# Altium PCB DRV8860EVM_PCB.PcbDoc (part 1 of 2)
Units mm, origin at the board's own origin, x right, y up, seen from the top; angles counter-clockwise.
Board outline 101 x 60 mm, 2 copper layers (Top Layer, Bottom Layer); 122 components, 87 nets, 449 pads, 90 vias.
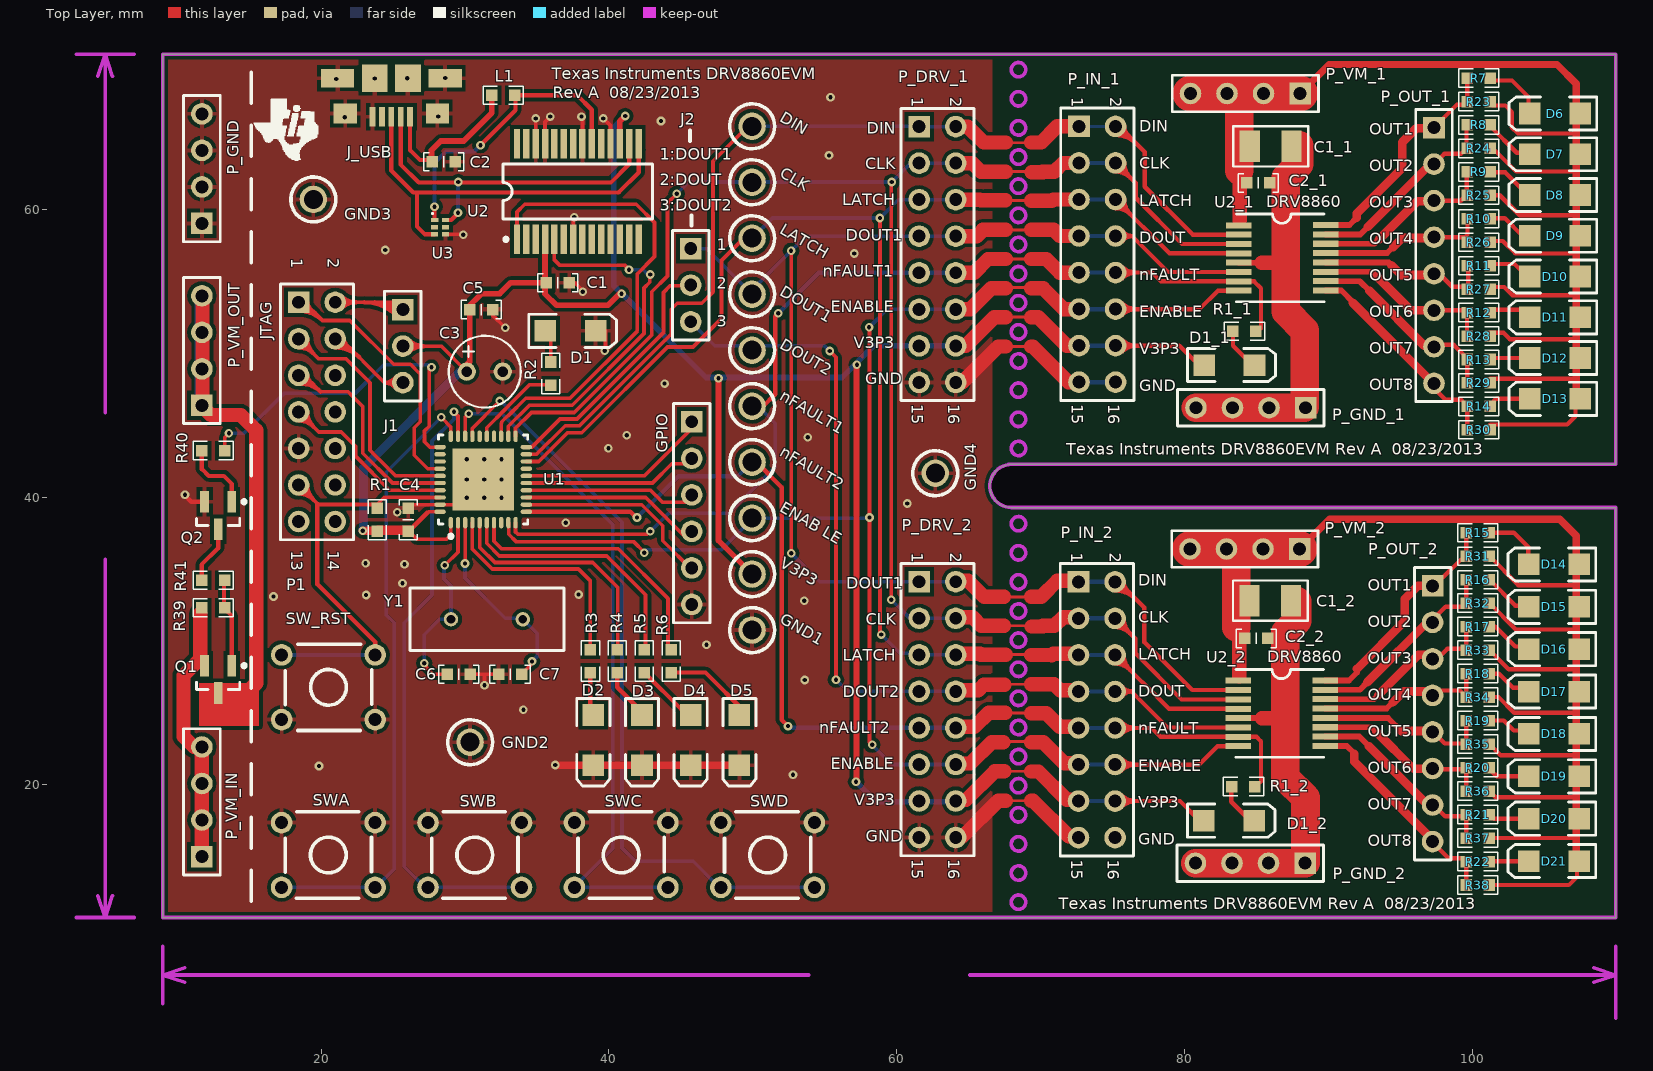
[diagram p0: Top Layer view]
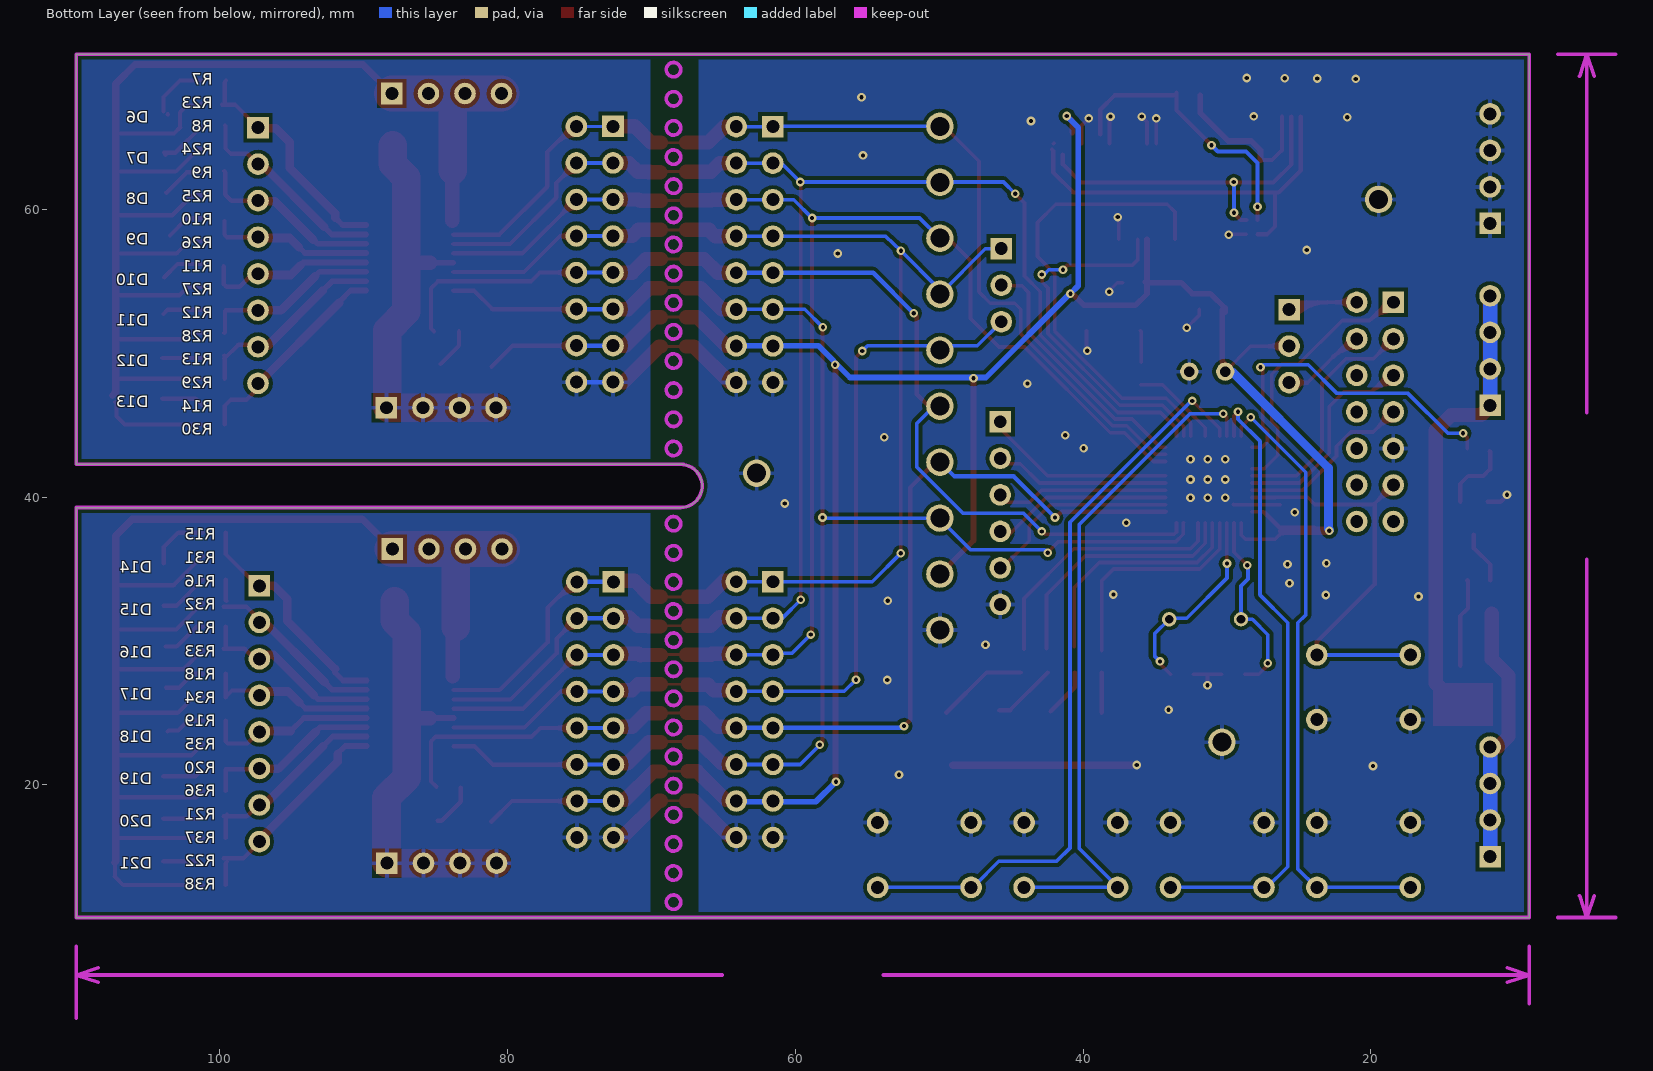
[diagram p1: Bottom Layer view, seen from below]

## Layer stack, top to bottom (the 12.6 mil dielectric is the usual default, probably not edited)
Top Layer: signal copper 0.0356
Dielectric: dielectric 0.32, FR-4, Dk 4.8
Bottom Layer: signal copper 0.0356

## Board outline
8.979,10.787 8.979,70.787 109.979,70.787 109.979,42.287 67.979,42.287 ccw(c67.979,40.787) 67.979,39.287 109.979,39.287 109.979,10.787

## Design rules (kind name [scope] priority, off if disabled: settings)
Clearance [All] p1: gap=0.2
PolygonConnect [(InPadClass('All Pads'))] p1: connectstyle=Relief reliefconductorwidth=0.3 reliefentries=4 polygonreliefangle="90 Angle" airgapwidth=0.254
PolygonConnect PolygonConnect_1 [All] p2: connectstyle=Direct reliefconductorwidth=0.254 reliefentries=4 polygonreliefangle="90 Angle" airgapwidth=0.254
RoutingVias [All] p1: holewidth=0.3 width=0.6 viastyle="Through Hole" minholewidth=0.25 minwidth=0.25 maxholewidth=0.711 maxwidth=1.27
SilkscreenOverComponentPads [All] p1: minsilkscreentomaskgap=0.254
SolderMaskExpansion [All] p1: expansion=0.102
Width [All] p1: maxlimit=3 minlimit=0.2 preferedwidth=0.254
27 further rules are at their usual default settings.

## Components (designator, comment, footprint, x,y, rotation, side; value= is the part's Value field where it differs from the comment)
C1 "Cap" C0603 36.437,54.907 r180 top
C1_1 "" 1210 84.546,64.398 r0 top
C1_2 "" 1210 84.519,32.809 r0 top
C2 "Cap" C0603 28.526,63.328 r180 top
C2_1 "" C0603 85.13,61.856 r0 top
C2_2 "" C0603 84.997,30.186 r0 top
C3 "Cap Pol1" CAP5MM 30.117,48.731 r0 top
C4 "Cap" C0603 26.053,38.444 r270 top
C5 "Cap" C0603 31.133,53.049 r0 top
C6 "Cap" C0603 29.567,27.7 r180 top
C7 "Cap" C0603 33.123,27.7 r0 top
CLK "IN1" TESTP 49.953,61.898 r0 top
D1 "Status" 3.2X1.6X1.1 37.324,51.57 r0 top
D1_1 "nFAULT" 3.2X1.6X1.1 83.126,49.191 r0 top
D1_2 "FAULTn" 3.2X1.6X1.1 83.111,17.516 r0 top
D2 "Status" 3.2X1.6X1.1 38.911,23.116 r270 top
D3 "Status" 3.2X1.6X1.1 42.296,23.116 r270 top
D4 "Status" 3.2X1.6X1.1 45.682,23.116 r270 top
D5 "Status" 3.2X1.6X1.1 49.068,23.116 r270 top
D6 "" 3.2X1.6X1.1 105.771,66.678 r180 top
D7 "" 3.2X1.6X1.1 105.771,63.845 r180 top
D8 "" 3.2X1.6X1.1 105.771,61.012 r180 top
D9 "" 3.2X1.6X1.1 105.771,58.179 r180 top
D10 "" 3.2X1.6X1.1 105.771,55.346 r180 top
D11 "" 3.2X1.6X1.1 105.771,52.513 r180 top
D12 "" 3.2X1.6X1.1 105.771,49.68 r180 top
D13 "" 3.2X1.6X1.1 105.771,46.847 r180 top
D14 "" 3.2X1.6X1.1 105.699,35.332 r180 top
D15 "" 3.2X1.6X1.1 105.699,32.385 r180 top
D16 "" 3.2X1.6X1.1 105.699,29.439 r180 top
D17 "" 3.2X1.6X1.1 105.699,26.493 r180 top
D18 "" 3.2X1.6X1.1 105.699,23.547 r180 top
D19 "" 3.2X1.6X1.1 105.699,20.601 r180 top
D20 "" 3.2X1.6X1.1 105.699,17.654 r180 top
D21 "" 3.2X1.6X1.1 105.699,14.708 r180 top
DIN "IN1" TESTP 49.953,65.79 r0 top
DOUT1 "IN1" TESTP 49.953,54.115 r90 top
DOUT2 "IN1" TESTP 49.953,50.223 r90 top
"ENAB LE" "IN1" TESTP 49.953,38.548 r90 top
GND1 "IN1" TESTP 49.953,30.765 r0 top
GND2 "IN1" TESTP 30.351,22.973 r90 top
GND3 "IN1" TESTP 19.451,60.706 r90 top
GND4 "IN1" TESTP 62.686,41.674 r90 top
GPIO "Header 6" HDR1X6 45.756,45.25 r270 top
J1 "PWR Select" HDR1X3 25.672,53.049 r270 top
J2 "DOUT Select" HDR1X3 45.685,57.283 r270 top
J_USB "USB Mini B Connector" "Micro USB AB" 24.87,66.455 r180 top
L1 "" R0603 32.643,67.94 r0 top
LATCH "IN1" TESTP 49.953,58.007 r90 top
nFAULT1 "IN1" TESTP 49.953,46.332 r90 top
nFAULT2 "IN1" TESTP 49.953,42.44 r90 top
P1 "JTAG" HDR2X7 18.433,53.557 r270 top
P_DRV_1 "Header 8X2" HDR2X8 61.569,65.767 r270 top
P_DRV_2 "Header 8X2" HDR2X8 61.569,34.129 r270 top
P_GND "Header 4" HDR1X4 11.705,59.036 r90 top
P_GND_1 "Header 4" HDR1X4 88.427,46.223 r180 top
P_GND_2 "Header 4" HDR1X4 88.392,14.562 r180 top
P_IN_1 "Header 8X2" HDR2X8 72.679,65.781 r270 top
P_IN_2 "Header 8X2" HDR2X8 72.644,34.12 r270 top
P_OUT_1 "TSW-108-07-G-S" HDR1X8 97.354,65.699 r270 top
P_OUT_2 "TSW-108-07-G-S" HDR1X8 97.259,33.847 r270 top
P_VM_1 "Header 4" HDR1X4 88.046,68.067 r180 top
P_VM_2 "Header 4" HDR1X4 88.011,36.406 r180 top
P_VM_IN "Header 4" HDR1X4 11.705,15.023 r90 top
P_VM_OUT "Header 4" HDR1X4 11.705,46.386 r90 top
Q1 "Si2319CDS" SOT-23 12.838,27.344 r270 top
Q2 "2N3904" SOT-23 12.838,38.738 r270 top
R1 "" R0603 23.894,38.444 r90 top
R1_1 "330" R0603 84.18,51.546 r180 top
R1_2 "330" R0603 84.111,19.886 r180 top
R2 "Res2" R0603 35.959,48.604 r270 top
R3 "Res2" R0603 38.71,28.616 r90 top
R4 "Res2" R0603 40.584,28.616 r90 top
R5 "Res2" R0603 42.457,28.616 r90 top
R6 "Res2" R0603 44.331,28.616 r90 top
R7 "10k" R0603 100.475,69.141 r180 top
R8 "10k" R0603 100.475,65.88 r180 top
R9 "10k" R0603 100.475,62.62 r180 top
R10 "10k" R0603 100.475,59.359 r180 top
R11 "10k" R0603 100.475,56.099 r180 top
R12 "10k" R0603 100.475,52.838 r180 top
R13 "10k" R0603 100.475,49.578 r180 top
R14 "10k" R0603 100.475,46.317 r180 top
R15 "10k" R0603 100.405,37.54 r180 top
R16 "10k" R0603 100.405,34.274 r180 top
R17 "10k" R0603 100.405,31.009 r180 top
R18 "10k" R0603 100.405,27.743 r180 top
R19 "10k" R0603 100.405,24.477 r180 top
R20 "10k" R0603 100.405,21.211 r180 top
R21 "10k" R0603 100.405,17.945 r180 top
R22 "10k" R0603 100.405,14.68 r180 top
R23 "27k" r0603 100.475,67.511 r0 top
R24 "27k" r0603 100.475,64.25 r0 top
R25 "27k" r0603 100.475,60.989 r0 top
R26 "27k" r0603 100.475,57.729 r0 top
R27 "27k" r0603 100.475,54.468 r0 top
R28 "27k" r0603 100.475,51.208 r0 top
R29 "27k" r0603 100.475,47.947 r0 top
R30 "27k" r0603 100.475,44.687 r0 top
R31 "27k" r0603 100.405,35.907 r0 top
R32 "27k" r0603 100.405,32.642 r0 top
R33 "27k" r0603 100.405,29.376 r0 top
R34 "27k" r0603 100.405,26.11 r0 top
R35 "27k" r0603 100.405,22.844 r0 top
R36 "27k" r0603 100.405,19.578 r0 top
R37 "27k" r0603 100.405,16.313 r0 top
R38 "27k" r0603 100.405,13.047 r0 top
R39 "" r0603 12.486,32.317 r180 top
R40 "" r0603 12.486,43.244 r180 top
R41 "" r0603 12.486,34.231 r0 top
SW_RST "MCU-RST" SWWW 20.502,26.792 r180 top
SWA "MCU-RST" SWWW 20.494,15.132 r0 top
SWB "MCU-RST" SWWW 30.673,15.132 r0 top
SWC "MCU-RST" SWWW 40.852,15.132 r0 top
SWD "MCU-RST" SWWW 51.03,15.132 r0 top
U1 "MSP430F2350" QFN40 31.26,41.238 r90 top
U2 "FT232RL-Reel" SSOP28 37.834,61.257 r0 top
U2_1 "Wolfteeth" WT 83.601,59.558 r270 top
U2_2 "Wolfteeth" WT 83.566,27.897 r270 top
U3 "TPD2E001DRYRG4" DRY0006A 28.26,58.776 r0 top
V3P3 "IN1" TESTP 49.953,34.657 r90 top
Y1 "8 MHZ" XTAL6 34.012,31.51 r180 top

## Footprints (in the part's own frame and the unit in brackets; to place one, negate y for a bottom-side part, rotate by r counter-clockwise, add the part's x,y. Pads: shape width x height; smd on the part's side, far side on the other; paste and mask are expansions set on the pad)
3.2X1.6X1.1 [mm] "SMT LED; 2 Flat Leads"
  rect 1.5x1.5 smd: 1(-1.75,0) 2(1.75,0)
  silkscreen extent -2.9,-1.15 3.2,1.15
1210 [mm]
  rect 1.4x2.2 smd: 1(0,0) 2(2.9,0)
  silkscreen extent -1.14,-1.4 4.06,1.4
C0603 [mm]
  rect 0.8x0.8 smd: 1(-0.8,0) 2(0.8,0)
  silkscreen extent -1.4,-0.64 1.4,0.64
CAP5MM [mil]
  round 50 hole 28: 1(0,0) 2(98.43,0)
  silkscreen extent -49,-98 148,98
DRY0006A [mm] "PSON, 6-Leads, Body 1x1.45mm, Pitch 0.5mm, TI Recommended"
  rect 0.52x0.3 smd paste+0 mask+0.05: 1(-0.385,0.5)
  rect 0.49x0.3 smd paste+0 mask+0.05: 2(-0.385,0) 3(-0.385,-0.5) 4(0.385,-0.5) 5(0.385,0) 6(0.385,0.5)
  silkscreen extent -0.57,0.9 -0.48,1, body extent -0.53,-0.75 0.53,0.75, height 0.6
HDR1X3 [mm] "Connector; Header; 3 Position"
  rect 1.5x1.5 hole 0.9: 1(0,0)
  round 1.5 hole 0.9: 2(2.54,0) 3(5.08,0)
  silkscreen extent -1.27,-1.27 6.35,1.27
HDR1X4 [mm] "Connector; Header; 4 Position"
  rect 1.5x1.5 hole 0.9: 1(0,0)
  round 1.5 hole 0.9: 2(2.54,0) 3(5.08,0) 4(7.62,0)
  silkscreen extent -1.27,-1.27 8.89,1.27
HDR1X6 [mm] "Connector; Header; 6 Position"
  rect 1.5x1.5 hole 0.9: 1(0,0)
  round 1.5 hole 0.9: 2(2.54,0) 3(5.08,0) 4(7.62,0) 5(10.16,0) 6(12.7,0)
  silkscreen extent -1.27,-1.27 13.97,1.27
HDR1X8 [mm] "Connector; Header; 8 Position"
  rect 1.5x1.5 hole 0.9: 1(0,0)
  round 1.5 hole 0.9: 2(2.54,0) 3(5.08,0) 4(7.62,0) 5(10.16,0) 6(12.7,0) 7(15.24,0) 8(17.78,0)
  silkscreen extent -1.27,-1.27 19.05,1.27
HDR2X7 [mm] "Connector; Header; 7x2 Position"
  rect 1.5x1.5 hole 0.9: 1(0,0)
  round 1.5 hole 0.9: 2(0,2.54) 3(2.54,0) 4(2.54,2.54) 5(5.08,0) 6(5.08,2.54) 7(7.62,0) 8(7.62,2.54) 9(10.16,0) 10(10.16,2.54) 11(12.7,0) 12(12.7,2.54) 13(15.24,0) 14(15.24,2.54)
  silkscreen extent -1.27,-1.27 16.51,3.81
HDR2X8 [mm] "Connector; Header; 8x2 Position"
  rect 1.5x1.5 hole 0.9: 1(0,0)
  round 1.5 hole 0.9: 2(0,2.54) 3(2.54,0) 4(2.54,2.54) 5(5.08,0) 6(5.08,2.54) 7(7.62,0) 8(7.62,2.54) 9(10.16,0) 10(10.16,2.54) 11(12.7,0) 12(12.7,2.54) 13(15.24,0) 14(15.24,2.54) 15(17.78,0) 16(17.78,2.54)
  silkscreen extent -1.27,-1.27 19.05,3.81
"Micro USB AB" [mm]
  rect 0.4x1.35 smd: 1(-1.3,0) 2(-0.65,0) 3(0,0) 4(0.65,0) 5(1.3,0)
  rect 2.3x1.3 smd: 5(-3.75,-2.675) 5(3.75,-2.675)
  rect 1.6x1.4 smd: 5(-3.2,-0.225) 5(3.2,-0.225)
  rect 1.8x1.9 smd: 5(-1.15,-2.675) 5(1.15,-2.675)
QFN40 [mm] "QFN, 40-Leads, Body 6x6mm, Pitch 0.5mm, IPC Medium Density"
  oval 0.8x0.3 smd: 1(-3,2.25) 2(-3,1.75) 3(-3,1.25) 4(-3,0.75) 5(-3,0.25) 6(-3,-0.25) 7(-3,-0.75) 8(-3,-1.25) 9(-3,-1.75) 10(-3,-2.25) 21(3,-2.25) 22(3,-1.75) 23(3,-1.25) 24(3,-0.75) 25(3,-0.25) 26(3,0.25) 27(3,0.75) 28(3,1.25) 29(3,1.75) 30(3,2.25)
  oval 0.3x0.8 smd: 11(-2.25,-3) 12(-1.75,-3) 13(-1.25,-3) 14(-0.75,-3) 15(-0.25,-3) 16(0.25,-3) 17(0.75,-3) 18(1.25,-3) 19(1.75,-3) 20(2.25,-3) 31(2.25,3) 32(1.75,3) 33(1.25,3) 34(0.75,3) 35(0.25,3) 36(-0.25,3) 37(-0.75,3) 38(-1.25,3) 39(-1.75,3) 40(-2.25,3)
  rect 4.3x4.3 smd: 41(0,0)
  silkscreen extent -4.07,-3.1 3.1,3.1, body extent -3.08,-3.08 3.08,3.08, height 0.8
R0603 [mm]
  rect 0.8x0.8 smd: 1(-0.8,0) 2(0.8,0)
  silkscreen extent -1.4,-0.64 1.4,0.64
r0603 [mm]
  rect 0.8x0.8 smd: 1(-0.8,0) 2(0.8,0)
  silkscreen extent -1.4,-0.64 1.4,0.64
SOT-23 [mm] "SOT23, 3-Leads, Body 2.9x1.3mm, Pitch 0.95mm, Lead Span 2.5mm, IPC Medium Density"
  rect 1.5x0.6 smd: 1(-0.95,0.95) 2(-0.95,-0.95) 3(0.95,0)
  silkscreen extent -1.07,-1.5 0.7,1.93, body extent -1.16,-1.45 1.21,1.45, height 1
SSOP28 [mm] "SSOP; 28 Leads; Body Width 5.3 mm; Pitch 0.65 mm"
  rect 0.45x2.05 smd: 1(-4.225,-3.325) 2(-3.575,-3.325) 3(-2.925,-3.325) 4(-2.275,-3.325) 5(-1.625,-3.325) 6(-0.975,-3.325) 7(-0.325,-3.325) 8(0.325,-3.325) 9(0.975,-3.325) 10(1.625,-3.325) 11(2.275,-3.325) 12(2.925,-3.325) 13(3.575,-3.325) 14(4.225,-3.325) 15(4.225,3.325) 16(3.575,3.325) 17(2.925,3.325) 18(2.275,3.325) 19(1.625,3.325) 20(0.975,3.325) 21(0.325,3.325) 22(-0.325,3.325) 23(-0.975,3.325) 24(-1.625,3.325) 25(-2.275,3.325) 26(-2.925,3.325) 27(-3.575,3.325) 28(-4.225,3.325)
  silkscreen extent -5.2,-3.45 5.2,1.9
SWWW [mm]
  round 1.5 hole 0.9: 1(-3.25,2.25) 1(3.25,2.25) 2(-3.25,-2.25) 2(3.25,-2.25)
  silkscreen extent -3,-3 3,3
TESTP [mil] "Glass Beaded Test Point"
  round 75 hole 52: 1(0,0)
  silkscreen extent -61,-61 62,61
WT [mm]
  rect 0.42x1.78 smd: 1(0.65,0.173) 2(1.3,0.173) 3(1.95,0.173) 4(2.6,0.173) 5(3.25,0.173) 6(3.9,0.173) 7(4.55,0.173) 8(5.2,0.173) 9(5.185,6.223) 10(4.535,6.223) 11(3.885,6.223) 12(3.235,6.223) 13(2.585,6.223) 14(1.935,6.223) 15(1.285,6.223) 16(0.635,6.223)
  silkscreen extent -0.13,0.03 5.97,6.1
XTAL6 [mm]
  round 1 hole 0.6: 1(-0.004,-0.007) 2(4.992,-0.01)
  silkscreen extent -2.87,-2.18 7.85,2.16

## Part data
C1 C2 C4 C5: "CAP .10UF 50V CERAMIC X7R 0805"
C1_1 C1_2: library part "Cap Pol1", "CAP ALUM 10UF 25V 20% RADIAL"
C2_1 C2_2: library part Cap, "Capacitor"
C3: "CAP ALUM 10UF 25V 20% RADIAL"
C6 C7: "CAP CERAMIC 33PF 50V NP0 0805"
CLK DIN DOUT1 DOUT2 "ENAB LE" GND1 GND2 GND3 GND4 LATCH nFAULT1 nFAULT2 V3P3: library part "TEST POINT", "PC TEST POINT MINIATURE SMT"
D1 D2 D3 D4 D5: library part LED3, "LED RED FACE UP 1206"
D1_1 D1_2 D6 D7 D8 D9 D10 D11 D12 D13 D14 D15 D16 D17 D18 D19 D20 D21: library part LED2, "LED RED FACE UP 1206"
GPIO: "Header, 6-Pin"
J1 J2: library part "Header 3", "CONN HEADER .100 SNGL STR 3POS"
J_USB: library part "USB Mini B Recepticle", "CONN RCPT MICRO USB TYPE AB"
L1: library part Inductor, "FERRITE 1.5A 40 OHM 0805 SMD"
P1: library part "Header 7X2H", "CONN HEADER .100 DUAL STR 14POS"
P_DRV_1 P_DRV_2 P_IN_1 P_IN_2: "Header, 8-Pin, Dual row"
P_GND P_GND_1 P_GND_2 P_VM_1 P_VM_2 P_VM_IN P_VM_OUT: "Header, 4-Pin"
P_OUT_1 P_OUT_2: "Header, TH, 100mil, 8x1, Gold plated, 230 mil above insulator"
Q1: library part SI2319DS-T1-E3, "MOSFET, P-CH, -40V, -2.3A, SOT-23"
Q2: library part "MMBT3904, Fairchild Semiconductor", "Transistor, NPN, 40V, 0.2A, SOT-23"
R1 R39 R40 R41: library part Res1, "RES 3.3K OHM 1/10W 5% 0603 SMD"
R1_1 R1_2 R7 R8 R9 R10 R11 R12 R13 R14 R15 R16 R17 R18 R19 R20 R21 R22 R23 R24 R25 R26 R27 R28 R29 R30 R31 R32 R33 R34 R35 R36 R37 R38: library part Res1, "Resistor"
R2 R3 R4 R5 R6: "RES 330 OHM 1/8W 5% 0805 SMD"
SW_RST SWA SWB SWC SWD: library part SW-PB, "SWITCH TACTILE SPST-NO 0.02A 15V"
U1: "IC MCU 16BIT 16K FLASH 40-QFN"
U2: "USB UART Asynchronous Serial Data Transfer Chip, SSOP-28, Tape and Reel"
U2_1 U2_2: library part wolfteeth
U3: "Low-Capacitance + / - 15 kV ESD-Protection Array for High-Speed Data Interfaces, 2 Channels, -40 to +85 degC, 6-pin SON (DRY), Green (RoHS & no Sb/Br)"
Y1: library part XTAL, "CRYSTAL 8.00 MHZ 20PF 49US"

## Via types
v1: diameter 0.6, hole 0.3, Top Layer to Bottom Layer, 90 vias

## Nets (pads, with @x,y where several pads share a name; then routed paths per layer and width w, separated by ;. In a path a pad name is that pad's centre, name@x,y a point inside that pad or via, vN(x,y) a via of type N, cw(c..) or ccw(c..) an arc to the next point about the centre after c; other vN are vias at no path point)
5VCC: L1.2 U2.20 U3.1 | length 19.7
  Top Layer w0.3: v1(27.874,60.203) 27.875,60.201 U3.1@27.875,59.276 ; v1(31.072,64.476) 33.502,66.906 L1.2@33.502,68.113 ; L1.2@33.547,67.957 37.788,67.957 38.806,66.94 U2.20@38.806,65.233
  Bottom Layer w0.3: v1(27.874,60.203) 27.874,63.244 28.672,64.042 30.638,64.042 v1(31.072,64.476)
CLK: CLK.1 P_DRV_1.3 P_DRV_1.4 P_DRV_2.3 P_DRV_2.4 P_IN_1.3 P_IN_1.4 P_IN_2.3 P_IN_2.4 U1.21 U2_1.3 U2_2.3 | length 129.1
  Top Layer w0.2: 67.475,62.64 69.421,62.64 ; 67.486,31.068 69.432,31.068
  Top Layer w0.254: U1.21@33.51,44.238 33.51,44.789 34.612,45.891 37.589,45.891 42.979,51.282 42.979,54.294 44.068,55.383 44.068,60.458 v1(44.705,61.095) ; v1(59.622,32.868) 59.622,61.884 v1(59.652,61.914)
  Top Layer w0.3: P_IN_2.4@75.057,31.707 P_IN_2.4@75.184,31.58 76.581,30.183 76.581,29.167 79.801,25.947 U2_2.3@83.739,25.947 ; P_IN_1.4@75.092,63.368 P_IN_1.4@75.219,63.241 76.616,61.844 76.616,60.828 79.836,57.608 U2_1.3@83.774,57.608 ; P_IN_2.4@75.184,30.98 cw(c75.184,29.532) 76.208,30.556 cw(c77.232,31.58) P_IN_2.4@75.784,31.58 ; P_IN_1.4@75.219,62.641 cw(c75.219,61.193) 76.243,62.217 cw(c77.267,63.241) P_IN_1.4@75.819,63.241
  Top Layer w1: P_DRV_1.4@64.109,63.227 65.271,63.227 65.861,62.637 67.592,62.637 ; P_DRV_2.4@64.119,31.655 65.282,31.655 65.88,31.057 67.463,31.057 ; 69.393,62.593 70.173,62.593 70.134,62.633 70.952,62.633 71.561,63.241 P_IN_1.3@72.679,63.241 ; 69.404,31.021 70.184,31.021 70.145,31.06 70.963,31.06 71.571,31.669 P_IN_2.3@72.689,31.669
  Bottom Layer w0.254: v1(44.705,61.095) 45.529,61.919 CLK.1@49.986,61.919 ; CLK.1@49.994,61.933 50.012,61.914 v1(59.652,61.914) 60.965,63.227 P_DRV_1.3@61.569,63.227 64.079,63.227 P_DRV_1.4@64.126,63.274 ; v1(59.622,32.868) 60.855,31.635 P_DRV_2.3@61.534,31.635 ; P_DRV_2.3@61.569,31.589 P_DRV_2.4@64.109,31.589 64.121,31.589 P_DRV_2.4@64.142,31.567 ; P_DRV_2.4@64.09,31.655 P_DRV_2.4@64.136,31.701
  Bottom Layer w0.3: P_IN_2.3@72.568,31.571 72.577,31.58 P_IN_2.3@72.644,31.58 P_IN_2.4@75.184,31.58 ; P_IN_1.3@72.827,63.213 72.856,63.241 P_IN_1.4@75.219,63.241
DIN: DIN.1 P_DRV_1.1 P_DRV_1.2 P_IN_1.1 P_IN_1.2 U1.19 U2_1.2 | length 73.6
  Top Layer w0.2: 67.592,64.663 67.608,64.647 69.554,64.647
  Top Layer w0.254: U1.19@34.26,42.988 34.972,42.988 36.96,44.976 37.957,44.976 44.328,51.347 44.328,53.063 44.757,53.491 46.447,53.491 47.233,54.278 47.233,63.361 DIN.1@49.743,65.871
  Top Layer w0.3: P_IN_1.2@75.219,65.181 cw(c75.219,63.12) 76.677,64.578 ; P_IN_1.2@75.219,65.481 cw(c75.219,64.144) 76.165,65.09 ; P_IN_1.2@75.6,65.654 77.251,64.003 77.251,61.59 80.583,58.258 U2_1.2@83.774,58.258 ; P_IN_1.2@75.819,65.781 ccw(c76.654,65.781) 76.063,65.191
  Top Layer w1: P_DRV_1.2@64.109,65.767 64.95,65.767 66.054,64.663 67.592,64.663 ; 69.352,64.663 70.046,64.663 71.165,65.781 P_IN_1.1@72.679,65.781
  Bottom Layer w0.2: P_IN_1.1@72.678,65.805 72.701,65.781 P_IN_1.2@75.219,65.781
  Bottom Layer w0.254: DIN.1@49.953,65.79 61.33,65.79 P_DRV_1.1@61.448,65.909 ; P_DRV_1.1@61.569,65.767 64.034,65.767 P_DRV_1.2@64.075,65.808
DOUT: J2.2 U1.20 | length 17.7
  Top Layer w0.254: U1.20@34.26,43.488 34.647,43.488 36.597,45.437 37.777,45.437 43.793,51.453 43.793,54.242 44.266,54.715 J2.2@45.63,54.715
DOUT1: DOUT1.1 J2.1 P_DRV_1.7 P_DRV_1.8 P_DRV_2.1 P_DRV_2.2 P_IN_1.7 P_IN_1.8 P_IN_2.1 P_IN_2.2 U2_1.6 U2_2.2 | length 107.4
  Top Layer w0.2: 67.587,58.576 69.533,58.576 ; 67.61,33.083 67.618,33.075 69.565,33.075
  Top Layer w0.254: J2.1@45.746,57.327 J2.1@45.804,57.269 ; DOUT1.1@49.86,54.461 50.184,54.461 50.271,54.548 DOUT1.1@50.653,54.166 ; v1(52.667,36.11) v1@52.667,57.009
  Top Layer w0.3: P_IN_2.2@75.184,33.52 cw(c75.184,31.459) 76.642,32.917 ; P_IN_2.2@75.184,33.82 cw(c75.184,32.483) 76.13,33.429 ; P_IN_1.8@75.219,58.161 76.362,58.161 ; P_IN_2.2@75.565,33.993 77.216,32.342 77.216,29.929 80.548,26.597 U2_2.2@83.739,26.597 ; P_IN_1.8@75.713,57.821 cw(c76.362,57.373) 76.362,58.161 ; P_IN_1.8@75.713,58.502 ccw(c76.362,58.95) 76.362,58.161 ; P_IN_2.2@75.784,34.12 ccw(c76.619,34.12) 76.029,33.53 ; U2_1.6@83.774,55.658 78.865,55.658 76.362,58.161
  Top Layer w1: P_DRV_1.8@64.109,58.147 65.581,58.147 66,58.566 65.981,58.586 67.592,58.586 ; P_DRV_2.2@64.119,34.195 64.96,34.195 66.078,33.077 67.463,33.077 ; 69.352,58.586 70.924,58.586 71.349,58.161 P_IN_1.7@72.679,58.161 ; 69.363,33.09 70.057,33.09 71.176,34.209 P_IN_2.1@72.689,34.209
  Bottom Layer w0.254: J2.1@45.652,57.276 46.792,57.276 DOUT1.1@49.953,54.115 ; DOUT1.1@50.015,53.919 50.015,54.486 v1(52.662,57.133) 53.728,58.147 P_DRV_1.7@61.569,58.147 P_DRV_1.8@64.109,58.147 64.2,58.147 P_DRV_1.8@64.361,57.986 ; v1@52.657,36.119 54.647,34.129 P_DRV_2.1@61.569,34.129 P_DRV_2.2@64.109,34.129 64.132,34.129 P_DRV_2.2@64.159,34.102 ; P_DRV_2.2@64.045,34.195 P_DRV_2.2@64.086,34.236
  Bottom Layer w0.3: P_IN_2.1@72.679,34.254 72.812,34.12 P_IN_2.2@75.184,34.12 ; P_IN_1.7@72.738,57.939 72.96,58.161 P_IN_1.8@75.219,58.161
DOUT2: DOUT2.1 J2.3 P_DRV_2.7 P_DRV_2.8 P_IN_2.7 P_IN_2.8 U2_2.6 | length 63.7
  Top Layer w0.2: 67.598,27.003 69.544,27.003
  Top Layer w0.254: v1(55.344,50.166) 55.782,49.728 v1(55.782,27.32)
  Top Layer w0.3: P_IN_2.7@72.644,26.5 P_IN_2.7@72.676,26.532 ; P_IN_2.8@75.678,26.16 cw(c76.327,25.712) 76.327,26.5 cw(c76.327,27.289) P_IN_2.8@75.678,26.841 ; 76.295,26.532 78.83,23.997 U2_2.6@83.739,23.997
  Top Layer w1: P_DRV_2.8@64.119,26.575 65.667,26.575 66.039,26.947 ; 66.042,26.962 67.501,26.962 ; 69.363,27.013 70.935,27.013 71.359,26.589 P_IN_2.7@72.689,26.589
  Bottom Layer w0.254: J2.3@45.709,52.174 47.351,50.531 54.979,50.531 v1(55.344,50.166) ; v1(55.782,27.32) 56.593,26.509 P_DRV_2.7@61.569,26.509 P_DRV_2.8@64.109,26.509 64.148,26.509 P_DRV_2.8@64.159,26.498 ; P_DRV_2.8@64.119,26.575 64.21,26.575 P_DRV_2.8@64.371,26.414 ; P_IN_2.7@73.096,26.609 P_IN_2.7@73.205,26.5
  Bottom Layer w0.3: P_IN_2.7@73.205,26.5 P_IN_2.8@75.184,26.5
ENABLE: "ENAB LE.1" P_DRV_1.11 P_DRV_1.12 P_DRV_2.11 P_DRV_2.12 P_IN_1.11 P_IN_1.12 P_IN_2.11 P_IN_2.12 U1.9 U2_1.8 U2_2.8 | length 117.3
  Top Layer w0.2: 67.506,54.582 69.452,54.582 ; 67.516,23.01 69.463,23.01
  Top Layer w0.254: U1.9@33.01,38.238 33.033,38.215 33.033,37.426 33.539,36.92 41.702,36.92 42.449,36.172 v1(42.449,36.15) ; v1(58.083,51.81) 58.117,51.777 58.117,22.972 v1(58.294,22.794)
  Top Layer w0.3: P_IN_2.11@72.644,21.42 P_IN_2.11@72.687,21.377 ; P_IN_1.12@75.219,53.081 81.061,53.081 82.338,54.358 U2_1.8@83.774,54.358 ; P_IN_2.12@75.542,21.494 75.625,21.411 81.017,21.411 82.303,22.697 U2_2.8@83.739,22.697 ; P_IN_2.12@75.608,20.996 cw(c76.632,19.972) 76.632,21.42 cw(c76.632,22.869) P_IN_2.12@75.608,21.845 ; P_IN_1.12@75.643,52.657 cw(c76.667,51.633) 76.667,53.081 cw(c76.667,54.53) P_IN_1.12@75.643,53.506
  Top Layer w1: P_DRV_1.12@64.109,53.067 65.111,53.067 66.578,54.534 67.592,54.534 ; P_DRV_2.12@64.119,21.495 65.122,21.495 66.602,22.975 67.417,22.975 ; 69.352,54.534 70.18,54.534 71.633,53.081 P_IN_1.11@72.679,53.081 ; 69.363,22.962 70.191,22.962 71.644,21.509 P_IN_2.11@72.689,21.509
  Bottom Layer w0.254: v1(42.449,36.15) 42.653,36.354 47.82,36.354 49.973,38.507 ; 49.953,38.548 58.069,38.548 v1(58.118,38.597) ; v1(58.083,51.81) 59.341,53.067 P_DRV_1.11@61.569,53.067 P_DRV_1.12@64.109,53.067 64.143,53.067 P_DRV_1.12@64.193,53.018 ; v1(58.294,22.794) 59.66,21.429 P_DRV_2.11@61.574,21.429 ; P_DRV_2.11@61.569,21.429 P_DRV_2.11@61.574,21.429 ; P_DRV_2.11@61.641,21.496 P_DRV_2.11@61.574,21.429 ; P_DRV_2.12@64.119,21.495 64.154,21.495 P_DRV_2.12@64.203,21.446 ; P_DRV_2.12@64.31,21.312 64.193,21.429 P_DRV_2.12@64.109,21.429 P_DRV_2.11@61.574,21.429
  Bottom Layer w0.3: P_IN_2.11@72.644,21.42 75.162,21.42 P_IN_2.12@75.222,21.481 ; P_IN_1.11@72.768,53.053 72.796,53.081 P_IN_1.12@75.219,53.081
GND: C1.1 C1_1.2 C1_2.2 C2.1 C2_1.2 C2_2.2 C3.2 C4.1 C5.2 C6.1 C7.1 D1.2 D2.2 D3.2 D4.2 D5.2 GND1.1 GND2.1 GND3.1 GND4.1 GPIO.6 J_USB.5 P1.9 P_DRV_1.15 P_DRV_1.16 P_DRV_2.15 P_DRV_2.16 P_GND.1 P_GND.2 P_GND.3 P_GND.4 P_GND_1.1 P_GND_1.2 P_GND_1.3 P_GND_1.4 P_GND_2.1 P_GND_2.2 P_GND_2.3 P_GND_2.4 P_IN_1.15 P_IN_1.16 P_IN_2.15 P_IN_2.16 Q2.2 SW_RST.1 SWA.1 SWB.1 SWC.1 SWD.1 U1.39 U1.41 U2.7 U2.18 U2.21 U2.25 U2.26 U2_1.5 U2_2.5 U3.4 | length 117.7
  Top Layer w0.2: 67.659,50.477 69.605,50.477 ; 67.669,18.905 69.615,18.905
  Top Layer w0.254: C4.1@26.297,39.488 U1.39@28.26,39.488 29.535,39.488 U1.41@29.553,39.506 ; U3.4@28.645,58.276 29.84,58.276 v1(29.869,58.247) ; C6.1@30.367,27.7 31.345,27.7 ; v1(31.345,26.938) 31.345,27.7 ; C5.2@31.933,53.049 31.933,52.63 v1(32.784,51.779) ; C7.1@32.323,27.7 31.345,27.7 ; U2.26@34.909,64.582 34.909,66.333 v1(34.913,66.337) ; U2.25@35.559,64.582 35.559,66.094 v1(35.929,66.464) ; C1.1@37.237,54.907 37.619,54.907 38.172,54.354 v1(38.172,54.282) ; U2.7@37.509,57.932 37.509,59.408 v1(37.58,59.479) ; v1(38.088,66.464) 38.159,66.393 U2.21@38.159,64.582 ; v1(39.612,66.337) 40.109,65.84 U2.18@40.109,64.582 ; v1(39.715,50.189) 39.762,50.236 D1.2@39.762,51.563
  Top Layer w0.3: v1(10.525,40.167) 10.525,40.121 10.959,39.688 Q2.2@11.888,39.688
  Top Layer w0.4: U2_2.5@83.739,24.647 85.401,24.648 ; U2_1.5@83.774,56.308 85.379,56.308
  Top Layer w0.5: v1(36.278,21.392) 36.304,21.366 D2.2@38.911,21.366 D5.2@49.068,21.366
  Top Layer w1: P_DRV_1.16@64.109,47.987 64.567,47.987 67.063,50.483 67.592,50.483 ; P_DRV_2.16@64.578,16.415 67.066,18.903 67.572,18.903 ; 69.352,50.483 69.465,50.483 71.946,48.001 P_IN_1.15@72.679,48.001 ; 69.363,18.911 69.475,18.911 P_IN_2.15@71.957,16.429 ; 85.379,56.308 86.724,56.308 ; 85.401,24.648 86.751,24.647 86.81,24.707
  Top Layer w2: P_GND_2.4@80.772,14.562 P_GND_2.3@83.312,14.562 P_GND_2.2@85.852,14.562 P_GND_2.1@88.392,14.562 88.405,14.562 88.43,14.588 88.43,19.105 87.019,20.517 87.019,30.594 87.844,31.42 C1_2.2@87.844,32.766 ; P_GND_1.4@80.807,46.223 P_GND_1.3@83.347,46.223 P_GND_1.2@85.887,46.223 88.331,46.223 88.377,46.27 88.377,51.586 87.048,52.915 87.048,62.224 87.992,63.168 C1_1.2@87.992,64.458
  Bottom Layer w0.3: P_IN_1.15@72.589,47.928 72.662,48.001 P_IN_1.15@72.679,48.001 P_IN_1.16@75.219,48.001
  other v1: 52.8,20.719 19.847,21.317 34.055,25.221 53.608,27.296 46.786,29.758 53.573,32.817 16.682,33.099 23.118,33.204 37.888,33.239 25.65,34.013 25.791,35.349 23.083,35.42 36.998,38.236 25.291,38.952 60.748,39.569 30.117,39.968 31.323,39.968 32.53,39.968 30.117,41.238 31.323,41.238 32.53,41.238 30.117,42.635 31.323,42.635 32.53,42.635 39.963,43.403 53.819,44.176 41.229,44.317 43.867,47.904 57.055,56.942 24.454,57.188 55.297,63.765 43.621,66.156 21.63,66.408 28.131,66.475 55.402,67.809 21.05,69.083 23.73,69.111 25.986,69.133 28.632,69.145
LATCH: LATCH.1 P_DRV_1.5 P_DRV_1.6 P_DRV_2.5 P_DRV_2.6 P_IN_1.5 P_IN_1.6 P_IN_2.5 P_IN_2.6 U1.18 U2_1.4 U2_2.4 | length 122.7
  Top Layer w0.2: 67.363,60.633 69.309,60.633 ; 67.374,29.061 69.32,29.061
  Top Layer w0.254: U1.18@34.26,42.488 35.114,42.488 37.117,44.491 38.114,44.491 44.075,50.451 45.843,50.451 47.825,52.433 47.825,56.465 49.494,58.134 LATCH.1@49.916,58.134 ; v1(58.837,59.411) 58.838,59.41 58.838,30.545 v1(58.928,30.455)
  Top Layer w0.3: P_IN_2.6@75.184,28.44 cw(c75.184,26.992) 76.208,28.016 cw(c77.232,29.04) P_IN_2.6@75.784,29.04 ; P_IN_2.6@75.184,29.04 78.927,25.297 U2_2.4@83.739,25.297 ; P_IN_1.6@75.219,60.101 cw(c75.219,58.653) 76.243,59.677 cw(c77.267,60.701) P_IN_1.6@75.819,60.701 ; P_IN_1.6@75.219,60.701 78.962,56.958 U2_1.4@83.774,56.958
  Top Layer w1: P_DRV_1.6@64.109,60.687 65.789,60.687 65.84,60.637 67.566,60.637 ; P_DRV_2.6@64.119,29.115 65.8,29.115 65.851,29.064 67.577,29.064 ; 69.352,60.611 70.759,60.611 70.775,60.595 70.881,60.701 P_IN_1.5@72.679,60.701 ; 69.363,29.039 70.769,29.039 70.785,29.023 70.891,29.129 P_IN_2.5@72.689,29.129
  Bottom Layer w0.254: LATCH.1@49.953,58.007 51.365,59.419 v1@58.846,59.419 ; v1(58.837,59.411) v1@58.846,59.419 ; v1@58.873,59.419 v1@58.846,59.419 ; v1(58.928,30.455) 60.216,29.167 61.44,29.167 P_DRV_2.5@61.541,29.066 ; P_DRV_2.5@61.569,29.049 P_DRV_2.6@64.109,29.049 64.143,29.049 P_DRV_2.6@64.226,28.965 ; P_DRV_2.6@64.054,29.115 P_DRV_2.6@64.237,28.932 ; P_DRV_1.6@64.226,60.504 64.043,60.687 P_DRV_1.5@61.569,60.687 60.114,60.687 v1@58.846,59.419
  Bottom Layer w0.3: P_IN_2.5@72.609,29.069 72.638,29.04 P_IN_2.5@72.644,29.04 P_IN_2.6@75.184,29.04 ; P_IN_1.5@72.648,60.621 72.729,60.701 P_IN_1.6@75.219,60.701
LED1: R3.2 U1.4 | length 15.8
  Top Layer w0.254: U1.4@30.51,38.238 30.51,36.393 31.888,35.015 37.877,35.015 38.712,34.18 R3.2@38.712,29.353
LED2: R4.2 U1.5 | length 16.6
  Top Layer w0.254: U1.5@31.01,38.238 31.01,36.535 32.076,35.469 38.874,35.469 40.616,33.727 R4.2@40.616,29.625
LED3: R5.2 U1.6 | length 17.7
  Top Layer w0.254: U1.6@31.51,38.238 31.51,36.797 32.384,35.923 39.847,35.923 42.542,33.228 R5.2@42.542,29.489
LED4: R6.2 U1.7 | length 18.6
  Top Layer w0.254: U1.7@32.01,38.238 32.01,36.939 32.533,36.415 40.646,36.415 44.105,32.956 R6.2@44.105,29.444
NetC2_2: C2.2 J_USB.1 L1.1 | length 11.3
  Top Layer w0.3: J_USB.1@26.17,66.455 26.17,64.133 26.862,63.44 C2.2@27.668,63.44
  Top Layer w0.4: C2.2@27.668,63.44 27.668,64.128 28.306,64.766 29.9,64.766 31.847,66.713 L1.1@31.847,67.94
NetC6_2: C6.2 U1.2 Y1.2 | length 13.6
  Top Layer w0.254: v1(27.154,28.462) 27.281,28.335 27.281,28.208 27.789,27.7 C6.2@28.767,27.7 ; v1(28.593,35.269) 29.51,36.186 U1.2@29.51,38.238
  Bottom Layer w0.254: v1(27.154,28.462) 27.154,30.445 28.229,31.52 Y1.2@29.02,31.52 29.02,33.837 28.539,34.318 v1@28.539,35.285
NetC7_2: C7.2 U1.3 Y1.1 | length 13.7
  Top Layer w0.254: v1(29.99,35.396) 30.01,35.416 U1.3@30.01,38.238 ; C7.2@33.923,27.7 34.647,28.424 v1(34.647,28.589)
  Bottom Layer w0.254: v1(29.99,35.396) 29.99,34.387 32.784,31.593 Y1.1@33.949,31.593 ; Y1.1@34.016,31.517 35.028,30.505 35.028,28.97 v1(34.647,28.589)
NetD1_1: D1.1 R2.1 | length 2.2
  Top Layer w0.254: R2.1@35.959,49.404 35.959,51.516 D1.1@36.013,51.571
NetD1_1_2: D1_1.2 R1_1.2 | length 2.8
  Top Layer w0.3: R1_1.2@83.38,51.546 83.38,50.535 D1_1.2@84.651,49.264
NetD1_2_2: D1_2.2 R1_2.2 | length 3.1
  Top Layer w0.3: R1_2.2@83.265,19.797 83.265,18.833 84.582,17.516 D1_2.2@84.861,17.516
NetD2_1: D2.1 R3.1 | length 2.8
  Top Layer w0.3: D2.1@38.702,25.021 38.71,25.029 R3.1@38.71,27.816
NetD3_1: D3.1 R4.1 | length 3.4
  Top Layer w0.3: R4.1@40.584,27.816 40.584,26.79 D3.1@42.243,25.131
NetD4_1: D4.1 R5.1 | length 4.4
  Top Layer w0.3: R5.1@42.457,27.816 45.07,25.204 D4.1@45.819,25.204
NetD5_1: D5.1 R6.1 | length 6.3
  Top Layer w0.3: R6.1@44.331,27.816 46.71,27.816 D5.1@49.505,25.021
NetD6_2: D6.2 R7.1 | length 4.1
  Top Layer w0.3: R7.1@101.275,68.968 102.783,68.968 103.926,67.825 D6.2@103.926,66.832 ; D6.2@103.615,66.636 D6.2@103.621,66.629
NetD7_2: D7.2 R8.1 | length 3.4
  Top Layer w0.3: R8.1@101.275,65.78 103.103,63.953 D7.2@103.89,63.953 ; D7.2@103.773,63.801 D7.2@103.779,63.794
NetD8_2: D8.2 R9.1 | length 3
  Top Layer w0.3: R9.1@101.275,62.593 102.299,62.593 D8.2@103.724,61.168
NetD9_2: D9.2 R10.1 | length 2.7
  Top Layer w0.3: R10.1@101.275,59.405 102.271,59.405 D9.2@103.475,58.2
NetD10_2: D10.2 R11.1 | length 3
  Top Layer w0.3: R11.1@101.275,56.217 102.955,56.217 D10.2@103.873,55.299
NetD11_2: D11.2 R12.1 | length 2.8
  Top Layer w0.3: R12.1@101.275,53.029 103.639,53.029 D11.2@103.923,52.745
NetD12_2: D12.2 R13.1 | length 2.8
  Top Layer w0.3: R13.1@101.259,49.698 101.276,49.68 D12.2@104.021,49.68
NetD13_2: D13.2 R14.1 | length 3
  Top Layer w0.3: R14.1@101.218,46.392 101.673,46.847 D13.2@104.021,46.847
NetD14_2: D14.2 R15.1 | length 4.3
  Top Layer w0.3: R15.1@101.205,37.54 102.907,37.54 103.906,36.542 D14.2@103.906,35.399
NetD15_2: D15.2 R16.1 | length 3.4
  Top Layer w0.3: R16.1@101.205,34.274 103.01,32.47 D15.2@103.906,32.47
NetD16_2: D16.2 R17.1 | length 3.1
  Top Layer w0.3: R17.1@101.205,31.009 101.615,31.009 103.003,29.621 D16.2@103.765,29.621
NetD17_2: D17.2 R18.1 | length 3
  Top Layer w0.3: R18.1@101.205,27.743 101.852,27.743 102.842,26.752 D17.2@103.745,26.752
